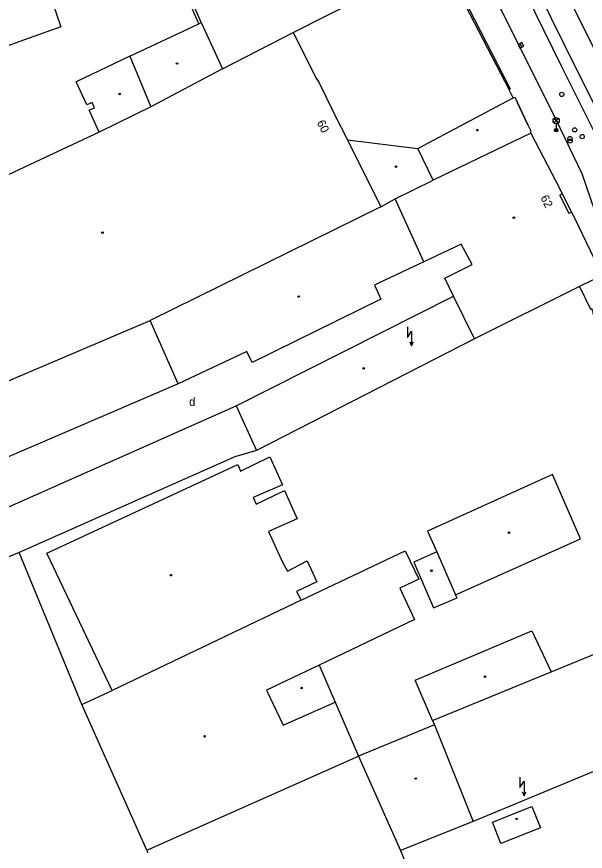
# Model space of a CAD drawing. Extents: x -598341 to -594502, y -1162301 to -1161406.
# Drawn here: x -597477.4 to -597409.8, y -1161848 to -1161748.9 of the extents above; entities that cross this region are included whole.
import ezdxf

# ---------------------------------------------------------------- set-up
doc = ezdxf.new("R2010")
doc.units = 0
for name, color, linetype in [('Vrstva 10', 7, 'Continuous'), ('Vrstva 11', 7, 'Continuous'), ('Vrstva 13', 7, 'Continuous'), ('Vrstva 27', 7, 'Continuous'), ('Vrstva 28', 7, 'Continuous'), ('Vrstva 33', 7, 'Continuous'), ('Vrstva 36', 7, 'Continuous'), ('Vrstva 39', 7, 'Continuous'), ('Vrstva 41', 7, 'Continuous'), ('Vrstva 46', 7, 'Continuous'), ('Vrstva 5', 7, 'Continuous'), ('Vrstva 6', 7, 'Continuous'), ('Vrstva 7', 7, 'Continuous'), ('Vrstva 8', 7, 'Continuous')]:
    doc.layers.add(name, color=color, linetype=linetype)

msp = doc.modelspace()

# ---------------------------------------------------------------- linework, layer by layer
at = {"layer": 'Vrstva 10'}
msp.add_line((-597413.3, -1161761.21), (-597410.23, -1161767.56), dxfattribs=at)
for points in [[(-597422.22, -1161743.25), (-597413.3, -1161761.21)], [(-597410.23, -1161767.56), (-597404.14, -1161785.35), (-597401.58, -1161792.6), (-597394.55, -1161806.99), (-597390.42, -1161815.33), (-597385.37, -1161822.82), (-597379.83, -1161831.05), (-597375.6, -1161837.3), (-597370.15, -1161848.42), (-597368.22, -1161852.29)]]:
    msp.add_lwpolyline(points, dxfattribs=at)
at = {"layer": 'Vrstva 11'}
for p, q in [((-597444.51, -1161750.78), (-597426.99, -1161741.92)), ((-597455.43, -1161749.61), (-597456.77, -1161746.44))]:
    msp.add_line(p, q, dxfattribs=at)
for points in [[(-597375.36, -1161830.11), (-597380.56, -1161819.58), (-597384.65, -1161811.14), (-597402.07, -1161775.92), (-597412.64, -1161754.81), (-597417.86, -1161744.11), (-597420.13, -1161739.67), (-597423.19, -1161733.58), (-597428.01, -1161724.62)], [(-597455.71, -1161749.76), (-597457.07, -1161746.65), (-597456.77, -1161746.44)]]:
    msp.add_lwpolyline(points, dxfattribs=at)
at = {"layer": 'Vrstva 13'}
for points in [[(-597372.12, -1161826.62), (-597376.34, -1161818.13), (-597388.64, -1161793.42), (-597398.12, -1161774.25), (-597409.67, -1161750.87), (-597418.39, -1161733.44), (-597422.33, -1161726)], [(-597425.21, -1161726.89), (-597421.25, -1161734.37), (-597415.51, -1161745.76), (-597412.33, -1161752.23), (-597400.82, -1161775.37), (-597383.06, -1161811.47), (-597379.23, -1161819.14), (-597374.33, -1161829)]]:
    msp.add_lwpolyline(points, dxfattribs=at)
at = {"layer": 'Vrstva 27'}
msp.add_line((-597417.583, -1161752.097), (-597417.358, -1161752.544), dxfattribs=at)
msp.add_lwpolyline([(-597417.806, -1161752.209), (-597417.581, -1161752.656), (-597417.135, -1161752.431), (-597417.359, -1161751.985)], close=True, dxfattribs=at)
at = {"layer": 'Vrstva 28'}
for centre in [(-597412.61, -1161758.15), (-597411.08, -1161762.36), (-597410.19, -1161763.16), (-597411.65, -1161763.39), (-597411.63, -1161763.68)]:
    msp.add_circle(centre, 0.25, dxfattribs=at)
at = {"layer": 'Vrstva 33'}
for p, q in [((-597413.545, -1161761.54), (-597413.015, -1161761.01)), ((-597413.545, -1161761.01), (-597413.015, -1161761.54)), ((-597413.28, -1161761.65), (-597413.28, -1161762.4))]:
    msp.add_line(p, q, dxfattribs=at)
for centre, radius in [((-597413.28, -1161761.275), 0.375), ((-597413.28, -1161762.4), 0.2), ((-597413.28, -1161762.4), 0.145), ((-597413.28, -1161762.4), 0.0876)]:
    msp.add_circle(centre, radius, dxfattribs=at)
at = {"layer": 'Vrstva 36'}
for points in [[(-597430.95, -1161785.76), (-597430.95, -1161787.01), (-597430.45, -1161786.26), (-597430.45, -1161788.01)], [(-597430.669, -1161787.521), (-597430.45, -1161788.01), (-597430.231, -1161787.521)], [(-597417.59, -1161839.23), (-597417.59, -1161840.48), (-597417.09, -1161839.73), (-597417.09, -1161841.48)], [(-597417.309, -1161840.991), (-597417.09, -1161841.48), (-597416.871, -1161840.991)]]:
    msp.add_lwpolyline(points, dxfattribs=at)
at = {"layer": 'Vrstva 39'}
for centre, radius in [((-597458.32, -1161754.48), 0.09), ((-597458.32, -1161754.48), 0.0398), ((-597465.11, -1161758.1), 0.09), ((-597465.11, -1161758.1), 0.0398), ((-597422.64, -1161762.4), 0.09), ((-597422.64, -1161762.4), 0.0398), ((-597432.29, -1161766.74), 0.09), ((-597432.29, -1161766.74), 0.0398), ((-597418.31, -1161772.78), 0.09), ((-597418.31, -1161772.78), 0.0398), ((-597467.16, -1161774.58), 0.09), ((-597467.16, -1161774.58), 0.0398), ((-597443.85, -1161782.16), 0.09), ((-597443.85, -1161782.16), 0.0398), ((-597436.14, -1161790.69), 0.09), ((-597436.14, -1161790.69), 0.0398), ((-597418.87, -1161810.21), 0.09), ((-597418.87, -1161810.21), 0.0398), ((-597459.04, -1161815.25), 0.09), ((-597459.04, -1161815.25), 0.0398), ((-597428.09, -1161814.71), 0.09), ((-597428.09, -1161814.71), 0.0398), ((-597421.72, -1161827.31), 0.09), ((-597421.72, -1161827.31), 0.0398), ((-597443.52, -1161828.66), 0.09), ((-597443.52, -1161828.66), 0.0398), ((-597455.04, -1161834.39), 0.09), ((-597455.04, -1161834.39), 0.0398), ((-597429.96, -1161839.41), 0.09), ((-597429.96, -1161839.41), 0.0398), ((-597417.98, -1161844.2), 0.09), ((-597417.98, -1161844.2), 0.0398)]:
    msp.add_circle(centre, radius, dxfattribs=at)
at = {"layer": 'Vrstva 5'}
for p, q in [((-597475.45, -1161740.3), (-597472.12, -1161750.11)), ((-597463.9, -1161753.61), (-597455.71, -1161749.76)), ((-597455.71, -1161749.76), (-597455.43, -1161749.61)), ((-597455.43, -1161749.61), (-597452.92, -1161755.11)), ((-597472.12, -1161750.11), (-597480.02, -1161752.93)), ((-597452.92, -1161755.11), (-597444.51, -1161750.78)), ((-597444.51, -1161750.78), (-597441.79, -1161756.21)), ((-597463.9, -1161753.61), (-597470.29, -1161756.67)), ((-597463.9, -1161753.61), (-597461.43, -1161759.61)), ((-597452.92, -1161755.11), (-597461.43, -1161759.61)), ((-597469.04, -1161759.4), (-597470.29, -1161756.67)), ((-597441.79, -1161756.21), (-597441.47, -1161756.69)), ((-597441.47, -1161756.69), (-597439.79, -1161760.1)), ((-597429.71, -1161764.57), (-597418.4, -1161758.55)), ((-597418.4, -1161758.55), (-597418.2, -1161758.47)), ((-597418.2, -1161758.47), (-597417.87, -1161759.17)), ((-597468.4, -1161759.1), (-597469.04, -1161759.4)), ((-597468.75, -1161760.03), (-597468.11, -1161759.74)), ((-597468.11, -1161759.74), (-597468.4, -1161759.1)), ((-597461.43, -1161759.61), (-597467.55, -1161762.64)), ((-597417.87, -1161759.17), (-597416.63, -1161761.77)), ((-597467.55, -1161762.64), (-597468.75, -1161760.03)), ((-597439.79, -1161760.1), (-597439.6, -1161760.52)), ((-597439.6, -1161760.52), (-597438.08, -1161763.53)), ((-597416.63, -1161761.77), (-597416.29, -1161762.49)), ((-597467.55, -1161762.64), (-597487.39, -1161771.93)), ((-597416.28, -1161762.74), (-597427.89, -1161768.35)), ((-597416.29, -1161762.49), (-597416.38, -1161762.53)), ((-597416.38, -1161762.53), (-597416.28, -1161762.74)), ((-597416.28, -1161762.74), (-597412.81, -1161769.44)), ((-597438.08, -1161763.53), (-597429.71, -1161764.57)), ((-597438.08, -1161763.53), (-597434.09, -1161771.5)), ((-597427.89, -1161768.35), (-597429.71, -1161764.57)), ((-597432.39, -1161770.54), (-597427.89, -1161768.35)), ((-597412.81, -1161769.44), (-597412.55, -1161769.96)), ((-597434.09, -1161771.5), (-597432.39, -1161770.54)), ((-597428.98, -1161778.03), (-597432.39, -1161770.54)), ((-597412.55, -1161769.96), (-597412.84, -1161770.1)), ((-597412.84, -1161770.1), (-597411.76, -1161772.26)), ((-597412.55, -1161769.96), (-597411.47, -1161772.12)), ((-597434.09, -1161771.5), (-597461.52, -1161785)), ((-597411.76, -1161772.26), (-597411.47, -1161772.12)), ((-597411.47, -1161772.12), (-597411.2, -1161772.67)), ((-597411.2, -1161772.67), (-597407.83, -1161779.67)), ((-597424.57, -1161775.94), (-597428.98, -1161778.03)), ((-597423.27, -1161778.37), (-597424.57, -1161775.94)), ((-597428.98, -1161778.03), (-597434.31, -1161780.55)), ((-597426.5, -1161779.96), (-597423.27, -1161778.37)), ((-597407.83, -1161779.67), (-597410.5, -1161780.95)), ((-597434.31, -1161780.55), (-597434.84, -1161780.8)), ((-597434.84, -1161780.8), (-597434.54, -1161781.48)), ((-597425.46, -1161782.13), (-597426.5, -1161779.96)), ((-597434.54, -1161781.48), (-597434.09, -1161782.48)), ((-597410.5, -1161780.95), (-597422.99, -1161787.17)), ((-597451.29, -1161795.14), (-597425.46, -1161782.13)), ((-597434.09, -1161782.48), (-597449.39, -1161790.01)), ((-597422.99, -1161787.17), (-597425.46, -1161782.13)), ((-597493.03, -1161798.44), (-597461.52, -1161785)), ((-597458.18, -1161792.53), (-597461.52, -1161785)), ((-597422.99, -1161787.17), (-597448.88, -1161800.45)), ((-597450.02, -1161788.7), (-597458.18, -1161792.53)), ((-597449.39, -1161790.01), (-597450.02, -1161788.7)), ((-597458.18, -1161792.53), (-597482.54, -1161802.98)), ((-597480.6, -1161808.15), (-597451.29, -1161795.14)), ((-597451.29, -1161795.14), (-597448.88, -1161800.45)), ((-597448.88, -1161800.45), (-597451.46, -1161801.21)), ((-597451.46, -1161801.21), (-597477.07, -1161812.56)), ((-597450.79, -1161802.89), (-597447.29, -1161801.2)), ((-597447.29, -1161801.2), (-597445.8, -1161804.52)), ((-597473.79, -1161812.63), (-597451.1, -1161802.1)), ((-597451.1, -1161802.1), (-597450.79, -1161802.89)), ((-597413.71, -1161803.3), (-597428.55, -1161810.01)), ((-597410.39, -1161810.93), (-597413.71, -1161803.3)), ((-597445.8, -1161804.52), (-597449.28, -1161806.03)), ((-597448.91, -1161806.83), (-597445.54, -1161805.19)), ((-597445.54, -1161805.19), (-597444.04, -1161808.55)), ((-597449.28, -1161806.03), (-597448.91, -1161806.83)), ((-597444.04, -1161808.55), (-597447.46, -1161810.07)), ((-597447.46, -1161810.07), (-597445.77, -1161813.72)), ((-597428.55, -1161810.01), (-597427.47, -1161812.48)), ((-597425.23, -1161817.57), (-597410.39, -1161810.93)), ((-597443.55, -1161818.23), (-597431.22, -1161812.35)), ((-597431.22, -1161812.35), (-597429.61, -1161815.72)), ((-597427.47, -1161812.48), (-597430.18, -1161813.72)), ((-597427.47, -1161812.48), (-597425.23, -1161817.57)), ((-597477.07, -1161812.56), (-597490.59, -1161818.24)), ((-597469.6, -1161830.62), (-597477.07, -1161812.56)), ((-597466.01, -1161828.94), (-597473.79, -1161812.63)), ((-597445.77, -1161813.72), (-597445.19, -1161814.76)), ((-597445.19, -1161814.76), (-597442.84, -1161813.54)), ((-597442.84, -1161813.54), (-597441.71, -1161816.04)), ((-597430.18, -1161813.72), (-597427.85, -1161819.13)), ((-597441.71, -1161816.04), (-597444.11, -1161817.18)), ((-597429.61, -1161815.72), (-597431.86, -1161816.8)), ((-597444.11, -1161817.18), (-597443.55, -1161818.23)), ((-597431.86, -1161816.8), (-597430.1, -1161820.53)), ((-597443.55, -1161818.23), (-597466.01, -1161828.94)), ((-597427.85, -1161819.13), (-597425.04, -1161817.94)), ((-597425.04, -1161817.94), (-597425.23, -1161817.57)), ((-597413.86, -1161826.74), (-597394.67, -1161818.85)), ((-597430.1, -1161820.53), (-597441.43, -1161825.94)), ((-597430.04, -1161827.74), (-597416.19, -1161821.88)), ((-597416.19, -1161821.88), (-597413.86, -1161826.74)), ((-597441.43, -1161825.94), (-597447.7, -1161828.93)), ((-597441.43, -1161825.94), (-597439.53, -1161830.35)), ((-597427.96, -1161832.53), (-597413.86, -1161826.74)), ((-597427.96, -1161832.53), (-597430.04, -1161827.74)), ((-597469.6, -1161830.62), (-597466.01, -1161828.94)), ((-597447.7, -1161828.93), (-597445.72, -1161833.08)), ((-597445.72, -1161833.08), (-597439.53, -1161830.35)), ((-597439.53, -1161830.35), (-597436.77, -1161836.74)), ((-597461.88, -1161847.9), (-597469.6, -1161830.62)), ((-597389.86, -1161830.69), (-597423.14, -1161844.49)), ((-597427.75, -1161833.04), (-597436.77, -1161836.74)), ((-597427.96, -1161832.53), (-597427.75, -1161833.04)), ((-597427.75, -1161833.04), (-597423.14, -1161844.49)), ((-597461.88, -1161847.9), (-597436.77, -1161836.74)), ((-597436.77, -1161836.74), (-597431.78, -1161847.94)), ((-597420.85, -1161844.6), (-597416.16, -1161842.73)), ((-597416.16, -1161842.73), (-597415.15, -1161845.25)), ((-597423.14, -1161844.49), (-597431.78, -1161847.94)), ((-597419.84, -1161847.13), (-597420.85, -1161844.6)), ((-597415.15, -1161845.25), (-597419.84, -1161847.13)), ((-597461.88, -1161847.9), (-597461.83, -1161848.25)), ((-597431.78, -1161847.94), (-597428.49, -1161855.81))]:
    msp.add_line(p, q, dxfattribs=at)
at = {"layer": 'Vrstva 6'}
for p, q in [((-597416.63, -1161761.77), (-597417.87, -1161759.17)), ((-597411.76, -1161772.26), (-597412.84, -1161770.1))]:
    msp.add_line(p, q, dxfattribs=at)
at = {"layer": 'Vrstva 7'}
msp.add_line((-597426.99, -1161741.92), (-597418.86, -1161757.59), dxfattribs=at)
for points in [[(-597426.52, -1161742.36), (-597418.74, -1161757.5), (-597418.86, -1161757.59)], [(-597410.5, -1161780.95), (-597409.19, -1161783.64), (-597409.1, -1161783.59), (-597408.88, -1161784.02), (-597408.97, -1161784.07), (-597407.65, -1161786.7), (-597407.56, -1161786.65), (-597407.36, -1161787.1), (-597407.79, -1161787.34)]]:
    msp.add_lwpolyline(points, dxfattribs=at)
at = {"layer": 'Vrstva 8'}
msp.add_line((-597418.4, -1161758.55), (-597418.86, -1161757.59), dxfattribs=at)

# ---------------------------------------------------------------- texts
at = {"layer": 'Vrstva 41'}
msp.add_text('d', height=1, dxfattribs=at).set_placement((-597456.887, -1161795.155))
at = {"layer": 'Vrstva 46'}
for s, p in [('60', (-597441.74, -1161761.49)), ('62', (-597415.18, -1161770.4))]:
    msp.add_text(s, height=1, rotation=296.39, dxfattribs=at).set_placement(p)

doc.saveas('drawing.dxf')
